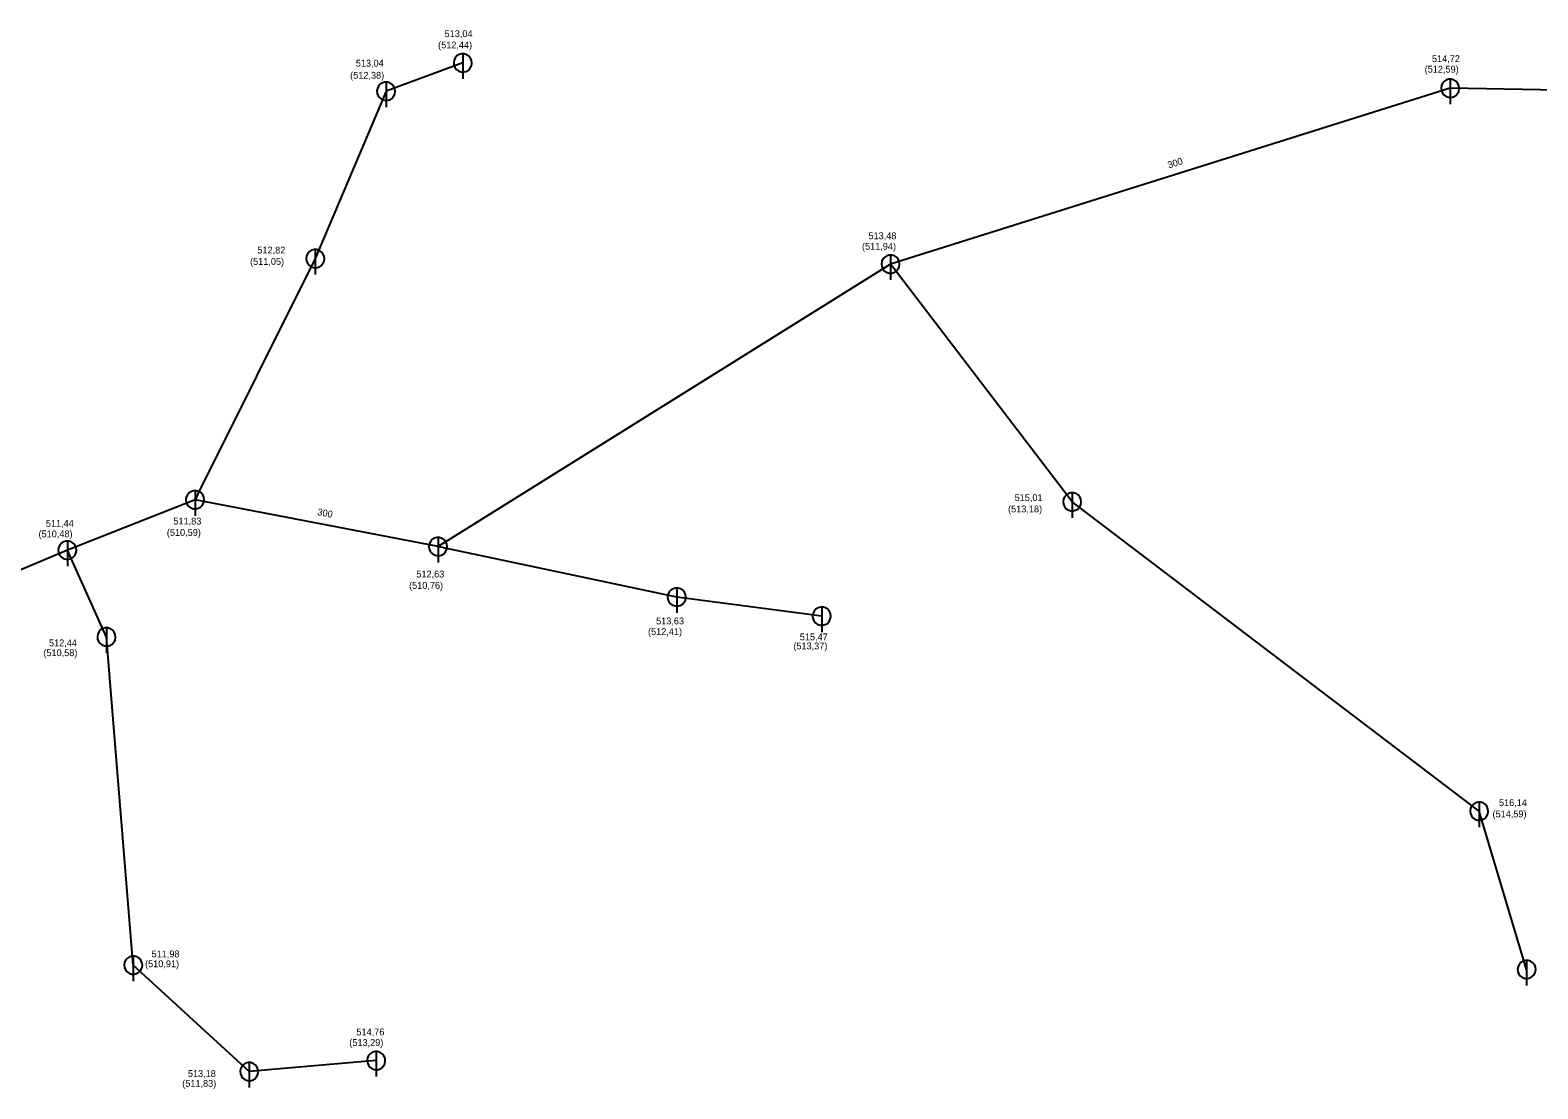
# Model space of a CAD drawing. Extents: x -476058 to -471893, y -1155786 to -1152000.
# Drawn here: x -474685.2 to -474519.6, y -1154109 to -1153992.7 of the extents above; entities that cross this region are included whole.
import ezdxf

# ---------------------------------------------------------------- set-up
doc = ezdxf.new("R2010")
doc.units = 0
for name, color, linetype in [('Vrstva 10', 7, 'Continuous'), ('Vrstva 18', 7, 'Continuous'), ('Vrstva 3', 7, 'Continuous'), ('Vrstva 4', 7, 'Continuous'), ('Vrstva 45', 7, 'Continuous'), ('Vrstva 50', 7, 'Continuous')]:
    doc.layers.add(name, color=color, linetype=linetype)

msp = doc.modelspace()

# ---------------------------------------------------------------- linework, layer by layer
at = {"layer": 'Vrstva 10'}
for p, q in [((-474637.69, -1153995.29), (-474637.69, -1153998.04)), ((-474646.12, -1153998.4), (-474646.12, -1154001.15)), ((-474529.26, -1153998.07), (-474529.26, -1154000.82)), ((-474653.89, -1154016.78), (-474653.89, -1154019.53)), ((-474590.72, -1154017.38), (-474590.72, -1154020.13)), ((-474667.09, -1154043.28), (-474667.09, -1154046.03)), ((-474570.77, -1154043.5), (-474570.77, -1154046.25)), ((-474681.11, -1154048.82), (-474681.11, -1154051.57)), ((-474640.41, -1154048.42), (-474640.41, -1154051.17)), ((-474614.2, -1154053.96), (-474614.2, -1154056.71)), ((-474598.27, -1154056.06), (-474598.27, -1154058.81)), ((-474676.82, -1154058.35), (-474676.82, -1154061.1)), ((-474526.07, -1154077.49), (-474526.07, -1154080.23)), ((-474673.88, -1154094.39), (-474673.88, -1154097.14)), ((-474520.86, -1154094.88), (-474520.86, -1154097.62)), ((-474647.2, -1154104.89), (-474647.2, -1154107.63)), ((-474661.14, -1154106.09), (-474661.14, -1154108.84))]:
    msp.add_line(p, q, dxfattribs=at)
for points in [[(-474636.69, -1153996.29), (-474636.73, -1153996.01), (-474636.85, -1153995.75), (-474637.03, -1153995.54), (-474637.27, -1153995.38), (-474637.54, -1153995.3), (-474637.82, -1153995.3), (-474638.09, -1153995.37), (-474638.33, -1153995.52), (-474638.52, -1153995.73), (-474638.65, -1153995.98), (-474638.69, -1153996.26), (-474638.66, -1153996.54), (-474638.55, -1153996.8), (-474638.38, -1153997.02), (-474638.14, -1153997.18), (-474637.88, -1153997.27), (-474637.59, -1153997.28), (-474637.32, -1153997.22), (-474637.08, -1153997.07), (-474636.88, -1153996.87), (-474636.75, -1153996.62), (-474636.7, -1153996.34), (-474636.69, -1153996.29)], [(-474645.12, -1153999.4), (-474645.16, -1153999.12), (-474645.27, -1153998.86), (-474645.46, -1153998.65), (-474645.69, -1153998.49), (-474645.96, -1153998.41), (-474646.24, -1153998.41), (-474646.52, -1153998.48), (-474646.76, -1153998.63), (-474646.95, -1153998.84), (-474647.07, -1153999.09), (-474647.12, -1153999.37), (-474647.09, -1153999.65), (-474646.98, -1153999.91), (-474646.8, -1154000.13), (-474646.57, -1154000.29), (-474646.3, -1154000.38), (-474646.02, -1154000.4), (-474645.74, -1154000.33), (-474645.5, -1154000.19), (-474645.3, -1153999.98), (-474645.17, -1153999.73), (-474645.12, -1153999.46), (-474645.12, -1153999.4)], [(-474528.26, -1153999.07), (-474528.3, -1153998.79), (-474528.42, -1153998.54), (-474528.6, -1153998.32), (-474528.84, -1153998.17), (-474529.11, -1153998.08), (-474529.39, -1153998.08), (-474529.66, -1153998.16), (-474529.9, -1153998.3), (-474530.09, -1153998.51), (-474530.21, -1153998.77), (-474530.26, -1153999.04), (-474530.23, -1153999.33), (-474530.12, -1153999.59), (-474529.94, -1153999.8), (-474529.71, -1153999.97), (-474529.44, -1154000.06), (-474529.16, -1154000.07), (-474528.89, -1154000), (-474528.64, -1153999.86), (-474528.45, -1153999.66), (-474528.32, -1153999.41), (-474528.26, -1153999.13), (-474528.26, -1153999.07)], [(-474652.89, -1154017.78), (-474652.93, -1154017.5), (-474653.05, -1154017.25), (-474653.23, -1154017.03), (-474653.47, -1154016.88), (-474653.74, -1154016.79), (-474654.02, -1154016.79), (-474654.29, -1154016.87), (-474654.53, -1154017.01), (-474654.72, -1154017.22), (-474654.84, -1154017.48), (-474654.89, -1154017.76), (-474654.86, -1154018.04), (-474654.75, -1154018.3), (-474654.57, -1154018.52), (-474654.34, -1154018.68), (-474654.07, -1154018.77), (-474653.79, -1154018.78), (-474653.52, -1154018.71), (-474653.27, -1154018.57), (-474653.08, -1154018.37), (-474652.95, -1154018.12), (-474652.89, -1154017.84), (-474652.89, -1154017.78)], [(-474589.72, -1154018.38), (-474589.76, -1154018.1), (-474589.88, -1154017.85), (-474590.06, -1154017.63), (-474590.29, -1154017.48), (-474590.57, -1154017.4), (-474590.85, -1154017.39), (-474591.12, -1154017.47), (-474591.36, -1154017.61), (-474591.55, -1154017.82), (-474591.67, -1154018.08), (-474591.72, -1154018.36), (-474591.69, -1154018.64), (-474591.58, -1154018.9), (-474591.4, -1154019.12), (-474591.17, -1154019.28), (-474590.9, -1154019.37), (-474590.62, -1154019.38), (-474590.35, -1154019.31), (-474590.1, -1154019.17), (-474589.91, -1154018.97), (-474589.78, -1154018.72), (-474589.72, -1154018.44), (-474589.72, -1154018.38)], [(-474666.09, -1154044.28), (-474666.13, -1154044), (-474666.25, -1154043.74), (-474666.43, -1154043.53), (-474666.67, -1154043.38), (-474666.94, -1154043.29), (-474667.22, -1154043.29), (-474667.49, -1154043.36), (-474667.73, -1154043.51), (-474667.92, -1154043.72), (-474668.05, -1154043.97), (-474668.09, -1154044.25), (-474668.06, -1154044.53), (-474667.95, -1154044.79), (-474667.78, -1154045.01), (-474667.54, -1154045.17), (-474667.28, -1154045.26), (-474666.99, -1154045.28), (-474666.72, -1154045.21), (-474666.48, -1154045.07), (-474666.28, -1154044.86), (-474666.15, -1154044.61), (-474666.1, -1154044.34), (-474666.09, -1154044.28)], [(-474569.77, -1154044.5), (-474569.81, -1154044.22), (-474569.92, -1154043.96), (-474570.11, -1154043.75), (-474570.34, -1154043.59), (-474570.61, -1154043.51), (-474570.9, -1154043.51), (-474571.17, -1154043.58), (-474571.41, -1154043.73), (-474571.6, -1154043.94), (-474571.72, -1154044.19), (-474571.77, -1154044.47), (-474571.74, -1154044.75), (-474571.63, -1154045.01), (-474571.45, -1154045.23), (-474571.22, -1154045.39), (-474570.95, -1154045.48), (-474570.67, -1154045.5), (-474570.39, -1154045.43), (-474570.15, -1154045.29), (-474569.96, -1154045.08), (-474569.83, -1154044.83), (-474569.77, -1154044.55), (-474569.77, -1154044.5)], [(-474680.11, -1154049.82), (-474680.15, -1154049.54), (-474680.27, -1154049.28), (-474680.45, -1154049.07), (-474680.69, -1154048.91), (-474680.96, -1154048.83), (-474681.24, -1154048.83), (-474681.51, -1154048.9), (-474681.75, -1154049.05), (-474681.94, -1154049.26), (-474682.07, -1154049.51), (-474682.11, -1154049.79), (-474682.08, -1154050.07), (-474681.97, -1154050.33), (-474681.79, -1154050.55), (-474681.56, -1154050.71), (-474681.3, -1154050.8), (-474681.01, -1154050.81), (-474680.74, -1154050.75), (-474680.5, -1154050.6), (-474680.3, -1154050.4), (-474680.17, -1154050.15), (-474680.11, -1154049.87), (-474680.11, -1154049.82)], [(-474639.41, -1154049.42), (-474639.45, -1154049.14), (-474639.57, -1154048.88), (-474639.75, -1154048.67), (-474639.98, -1154048.52), (-474640.26, -1154048.43), (-474640.54, -1154048.43), (-474640.81, -1154048.5), (-474641.05, -1154048.65), (-474641.24, -1154048.86), (-474641.36, -1154049.11), (-474641.41, -1154049.39), (-474641.38, -1154049.67), (-474641.27, -1154049.93), (-474641.09, -1154050.15), (-474640.86, -1154050.31), (-474640.59, -1154050.4), (-474640.31, -1154050.42), (-474640.04, -1154050.35), (-474639.79, -1154050.21), (-474639.6, -1154050), (-474639.47, -1154049.75), (-474639.41, -1154049.48), (-474639.41, -1154049.42)], [(-474613.2, -1154054.96), (-474613.23, -1154054.68), (-474613.35, -1154054.42), (-474613.54, -1154054.21), (-474613.77, -1154054.05), (-474614.04, -1154053.97), (-474614.32, -1154053.97), (-474614.6, -1154054.04), (-474614.84, -1154054.19), (-474615.03, -1154054.4), (-474615.15, -1154054.65), (-474615.2, -1154054.93), (-474615.16, -1154055.21), (-474615.05, -1154055.47), (-474614.88, -1154055.69), (-474614.65, -1154055.85), (-474614.38, -1154055.94), (-474614.1, -1154055.96), (-474613.82, -1154055.89), (-474613.58, -1154055.75), (-474613.38, -1154055.54), (-474613.25, -1154055.29), (-474613.2, -1154055.02), (-474613.2, -1154054.96)], [(-474597.27, -1154057.06), (-474597.31, -1154056.78), (-474597.43, -1154056.53), (-474597.61, -1154056.31), (-474597.85, -1154056.16), (-474598.12, -1154056.07), (-474598.4, -1154056.07), (-474598.67, -1154056.15), (-474598.91, -1154056.29), (-474599.1, -1154056.5), (-474599.22, -1154056.76), (-474599.27, -1154057.03), (-474599.24, -1154057.31), (-474599.13, -1154057.57), (-474598.95, -1154057.79), (-474598.72, -1154057.96), (-474598.45, -1154058.05), (-474598.17, -1154058.06), (-474597.9, -1154057.99), (-474597.65, -1154057.85), (-474597.46, -1154057.65), (-474597.33, -1154057.4), (-474597.27, -1154057.12), (-474597.27, -1154057.06)], [(-474675.82, -1154059.35), (-474675.86, -1154059.07), (-474675.98, -1154058.81), (-474676.16, -1154058.6), (-474676.4, -1154058.45), (-474676.67, -1154058.36), (-474676.95, -1154058.36), (-474677.22, -1154058.43), (-474677.46, -1154058.58), (-474677.65, -1154058.79), (-474677.77, -1154059.04), (-474677.82, -1154059.32), (-474677.79, -1154059.6), (-474677.68, -1154059.86), (-474677.5, -1154060.08), (-474677.27, -1154060.24), (-474677, -1154060.33), (-474676.72, -1154060.35), (-474676.45, -1154060.28), (-474676.2, -1154060.14), (-474676.01, -1154059.93), (-474675.88, -1154059.68), (-474675.82, -1154059.41), (-474675.82, -1154059.35)], [(-474525.07, -1154078.49), (-474525.11, -1154078.21), (-474525.23, -1154077.95), (-474525.41, -1154077.73), (-474525.65, -1154077.58), (-474525.92, -1154077.5), (-474526.2, -1154077.49), (-474526.47, -1154077.57), (-474526.71, -1154077.72), (-474526.9, -1154077.93), (-474527.03, -1154078.18), (-474527.07, -1154078.46), (-474527.04, -1154078.74), (-474526.93, -1154079), (-474526.76, -1154079.22), (-474526.52, -1154079.38), (-474526.26, -1154079.47), (-474525.97, -1154079.48), (-474525.7, -1154079.41), (-474525.46, -1154079.27), (-474525.26, -1154079.07), (-474525.13, -1154078.82), (-474525.08, -1154078.54), (-474525.07, -1154078.49)], [(-474672.88, -1154095.39), (-474672.92, -1154095.11), (-474673.04, -1154094.85), (-474673.22, -1154094.64), (-474673.46, -1154094.49), (-474673.73, -1154094.4), (-474674.01, -1154094.4), (-474674.28, -1154094.47), (-474674.52, -1154094.62), (-474674.71, -1154094.83), (-474674.83, -1154095.08), (-474674.88, -1154095.36), (-474674.85, -1154095.64), (-474674.74, -1154095.9), (-474674.56, -1154096.12), (-474674.33, -1154096.28), (-474674.06, -1154096.37), (-474673.78, -1154096.39), (-474673.51, -1154096.32), (-474673.26, -1154096.18), (-474673.07, -1154095.97), (-474672.94, -1154095.72), (-474672.88, -1154095.45), (-474672.88, -1154095.39)], [(-474519.86, -1154095.88), (-474519.9, -1154095.6), (-474520.01, -1154095.34), (-474520.2, -1154095.13), (-474520.43, -1154094.97), (-474520.7, -1154094.89), (-474520.98, -1154094.89), (-474521.26, -1154094.96), (-474521.49, -1154095.11), (-474521.68, -1154095.32), (-474521.81, -1154095.57), (-474521.86, -1154095.85), (-474521.82, -1154096.13), (-474521.72, -1154096.39), (-474521.54, -1154096.61), (-474521.31, -1154096.77), (-474521.04, -1154096.86), (-474520.76, -1154096.87), (-474520.48, -1154096.8), (-474520.24, -1154096.66), (-474520.04, -1154096.46), (-474519.91, -1154096.21), (-474519.86, -1154095.93), (-474519.86, -1154095.88)], [(-474646.2, -1154105.89), (-474646.23, -1154105.61), (-474646.35, -1154105.35), (-474646.54, -1154105.13), (-474646.77, -1154104.98), (-474647.04, -1154104.9), (-474647.32, -1154104.89), (-474647.6, -1154104.97), (-474647.84, -1154105.12), (-474648.03, -1154105.32), (-474648.15, -1154105.58), (-474648.2, -1154105.86), (-474648.16, -1154106.14), (-474648.05, -1154106.4), (-474647.88, -1154106.62), (-474647.65, -1154106.78), (-474647.38, -1154106.87), (-474647.1, -1154106.88), (-474646.82, -1154106.81), (-474646.58, -1154106.67), (-474646.38, -1154106.47), (-474646.25, -1154106.22), (-474646.2, -1154105.94), (-474646.2, -1154105.89)], [(-474660.14, -1154107.09), (-474660.18, -1154106.81), (-474660.3, -1154106.55), (-474660.48, -1154106.34), (-474660.72, -1154106.19), (-474660.99, -1154106.1), (-474661.27, -1154106.1), (-474661.54, -1154106.17), (-474661.78, -1154106.32), (-474661.97, -1154106.53), (-474662.1, -1154106.78), (-474662.14, -1154107.06), (-474662.11, -1154107.34), (-474662, -1154107.6), (-474661.83, -1154107.82), (-474661.59, -1154107.98), (-474661.33, -1154108.07), (-474661.04, -1154108.09), (-474660.77, -1154108.02), (-474660.53, -1154107.88), (-474660.33, -1154107.67), (-474660.2, -1154107.42), (-474660.15, -1154107.15), (-474660.14, -1154107.09)]]:
    msp.add_lwpolyline(points, dxfattribs=at)
at = {"layer": 'Vrstva 45'}
for points in [[(-474529.26, -1153999.07), (-474590.72, -1154018.38)], [(-474455.89, -1154000.42), (-474529.26, -1153999.07)], [(-474590.72, -1154018.38), (-474640.41, -1154049.42)], [(-474667.09, -1154044.28), (-474681.11, -1154049.82)], [(-474640.41, -1154049.42), (-474667.09, -1154044.28)], [(-474681.11, -1154049.82), (-474700.93, -1154058.16)]]:
    msp.add_lwpolyline(points, dxfattribs=at)
at = {"layer": 'Vrstva 50'}
for points in [[(-474637.69, -1153996.29), (-474646.12, -1153999.4), (-474653.89, -1154017.78)], [(-474653.89, -1154017.78), (-474666.77, -1154043.63)], [(-474590.31, -1154018.92), (-474590.72, -1154018.38)], [(-474570.77, -1154044.5), (-474590.31, -1154018.92)], [(-474666.77, -1154043.63), (-474667.09, -1154044.28)], [(-474526.07, -1154078.49), (-474570.77, -1154044.5)], [(-474676.82, -1154059.35), (-474680.85, -1154050.41), (-474681.11, -1154049.82)], [(-474639.64, -1154049.58), (-474640.41, -1154049.42)], [(-474614.2, -1154054.96), (-474639.64, -1154049.58)], [(-474598.27, -1154057.06), (-474614.2, -1154054.96)], [(-474673.88, -1154095.39), (-474676.82, -1154059.35)], [(-474520.86, -1154095.88), (-474526.07, -1154078.49)], [(-474661.14, -1154107.09), (-474673.88, -1154095.39)], [(-474647.2, -1154105.89), (-474661.14, -1154107.09)]]:
    msp.add_lwpolyline(points, dxfattribs=at)

# ---------------------------------------------------------------- texts
at = {"layer": 'Vrstva 18'}
for rotation, p in [(17.4435, (-474560.15, -1154007.88)), (349.097, (-474653.7, -1154045.95))]:
    msp.add_text('300 ', height=0.75, rotation=rotation, dxfattribs=at).set_placement(p)
at = {"layer": 'Vrstva 3'}
for s, p in [('513,04', (-474639.69, -1153993.45)), ('514,72', (-474531.26, -1153996.19)), ('513,04', (-474649.44, -1153996.69)), ('513,48', (-474593.14, -1154015.65)), ('512,82', (-474660.25, -1154017.22)), ('515,01', (-474577.09, -1154044.41)), ('511,44', (-474683.48, -1154047.24)), ('511,83', (-474669.47, -1154046.99)), ('512,63', (-474642.79, -1154052.81)), ('513,63', (-474616.46, -1154057.96)), ('512,44', (-474683.13, -1154060.37)), ('515,47', (-474600.68, -1154059.71)), ('516,14', (-474523.9, -1154077.92)), ('511,98', (-474671.87, -1154094.54)), ('514,76', (-474649.37, -1154103.11)), ('513,18', (-474667.88, -1154107.68))]:
    msp.add_text(s, height=0.75, dxfattribs=at).set_placement(p)
at = {"layer": 'Vrstva 4'}
for s, p in [('(512,44)', (-474640.4, -1153994.69)), ('(512,38)', (-474650.06, -1153998.02)), ('(512,59)', (-474532.06, -1153997.35)), ('(511,94)', (-474593.85, -1154016.81)), ('(511,05)', (-474661.05, -1154018.47)), ('(513,18)', (-474577.81, -1154045.66)), ('(510,48)', (-474684.28, -1154048.4)), ('(510,59)', (-474670.19, -1154048.24)), ('(510,76)', (-474643.59, -1154054.06)), ('(512,41)', (-474617.35, -1154059.13)), ('(513,37)', (-474601.39, -1154060.71)), ('(510,58)', (-474683.75, -1154061.45)), ('(514,59)', (-474524.61, -1154079.16)), ('(510,91)', (-474672.58, -1154095.62)), ('(513,29)', (-474650.15, -1154104.27)), ('(511,83)', (-474668.5, -1154108.76))]:
    msp.add_text(s, height=0.75, dxfattribs=at).set_placement(p)

doc.saveas('drawing.dxf')
